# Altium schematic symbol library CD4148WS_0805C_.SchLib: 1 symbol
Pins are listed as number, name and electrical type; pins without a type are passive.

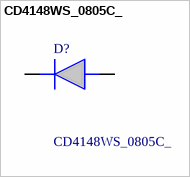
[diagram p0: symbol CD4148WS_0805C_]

## CD4148WS_0805C_
designator D?
CD4148WS(0805C); Diode: switching; SMD; 100V; 0.15A; 4ns; 0805; Ufmax: 1V; Ifsm: 0.5A; Manufacturer_Name: DC COMPONENTS CO., LTD; Geometry.Height: 0.95mm
footprint DIOC2012X95N
pins: 1 K, 2 A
